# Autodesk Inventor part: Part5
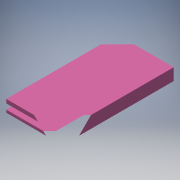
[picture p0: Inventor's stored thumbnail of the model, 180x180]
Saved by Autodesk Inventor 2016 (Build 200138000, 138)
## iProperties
Created: 2020-04
Part Number: Part5
Material: Generic
Document SubType Name: Modeling
Designer: merlin
Density: 1 g/cm^3
Appearance: Pink
Author: merlin
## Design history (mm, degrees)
sketch "Sketch1"
  geometry: L1 (30.162, 34.925)-(0, 34.925); L2 (0, 34.925)-(0, -225.425); L3 (0, -225.425)-(30.162, -225.425); L4 (30.162, -225.425)-(30.162, 34.925); 1 further point
  constraints: 8 end point, 2 parallel, 1 horizontal, 1 perpendicular
extrude "Extrusion1" new body sketch "Sketch1" distance "d0" = 27.94; taper "d1" = 0 deg
sketch "Sketch2"
  geometry: L1 (0, 0)-(0, 27.94) reference; L2 (260.35, 27.94)-(0, 27.94); L3 (0, 27.94)-(0, 19.05); L4 (0, 19.05)-(260.35, 19.05); L5 (260.35, 19.05)-(260.35, 27.94); 1 further point
  constraints: 8 end point, 2 parallel, 1 horizontal, 1 perpendicular, 1 point on line
extrude "Extrusion2" join sketch "Sketch2" distance "d2" = 101.6; taper "d3" = 0 deg
sketch "Sketch3"
  geometry: L1 (260.35, 0)-(260.35, 27.94) reference; L2 (0, 0)-(0, 27.94) reference; L3 (260.35, 0)-(0, 0); L4 (0, 0)-(0, 6.35); L5 (0, 6.35)-(260.35, 6.35); L6 (260.35, 6.35)-(260.35, 0); 1 further point
  constraints: 8 end point, 2 parallel, 1 horizontal, 1 perpendicular, 1 point on line
extrude "Extrusion3" join sketch "Sketch3" distance "d4" = 101.6; taper "d5" = 0 deg
body "Solid1"
